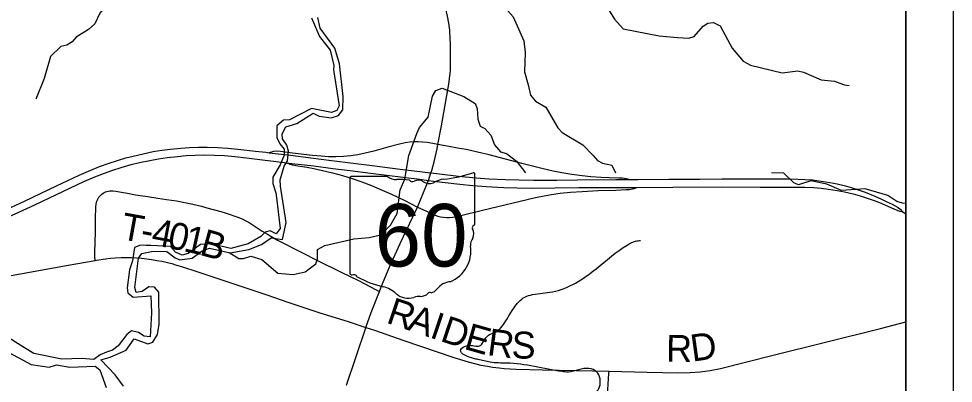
# Model space of a CAD drawing. Extents: x 0 to 34, y 0 to 22.
# Drawn here: x 28.944 to 30.917, y 17.017 to 17.785 of the extents above; entities that cross this region are included whole.
import ezdxf

# ---------------------------------------------------------------- set-up
doc = ezdxf.new("R2010")
doc.units = 0
for name, color, linetype in [('GM_X_Adjacent_County', 7, 'Continuous'), ('GM_X_County', 7, 'Continuous'), ('GM_X_County_Road', 7, 'Continuous'), ('GM_X_County_Road_Text', 7, 'Continuous'), ('GM_X_Interchange_Ramps', 7, 'Continuous'), ('GM_X_Minor_River', 7, 'Continuous'), ('GM_X_State_Location', 7, 'Continuous'), ('GM_X_State_Route', 7, 'Continuous'), ('GM_X_State_Shield', 7, 'Continuous'), ('GM_X_Township', 7, 'Continuous'), ('GM_X_Township_Road', 7, 'Continuous'), ('GM_X_Township_Road_Text', 7, 'Continuous'), ('SH_Data', 7, 'Continuous')]:
    doc.layers.add(name, color=color, linetype=linetype)

msp = doc.modelspace()

# ---------------------------------------------------------------- linework, layer by layer
at = {"layer": 'GM_X_Adjacent_County'}
msp.add_lwpolyline([(24.0167, 18.0693), (24.0167, 14.1), (30.8167, 14.1), (30.8167, 17.8174)], dxfattribs=at)
at = {"layer": 'GM_X_County'}
msp.add_lwpolyline([(24.0167, 18.0693), (24.0167, 14.1), (30.8167, 14.1), (30.8167, 17.8174)], dxfattribs=at)
at = {"layer": 'GM_X_County_Road'}
for points in [[(29.1052, 17.2759), (29.1086, 17.2765), (29.1274, 17.2793), (29.1381, 17.2807), (29.1477, 17.2813), (29.1602, 17.2819), (29.1819, 17.2817), (29.2036, 17.2803), (29.2146, 17.2791), (29.2247, 17.2777), (29.2359, 17.2758), (29.2464, 17.274), (29.2676, 17.269), (29.2773, 17.266), (29.2881, 17.2628), (29.3224, 17.2516), (29.468, 17.203), (29.5121, 17.188), (29.58, 17.1655), (29.6393, 17.147), (29.6771, 17.1346)], [(28.37, 17.1425), (28.4294, 17.1534), (28.6221, 17.1878), (28.7381, 17.2094), (28.8329, 17.2261), (28.8849, 17.2357), (28.9245, 17.2432), (28.9826, 17.2537), (29.0529, 17.2667), (29.1052, 17.2759)], [(30.19, 17.0422), (30.2702, 17.0401), (30.3355, 17.0389), (30.3604, 17.0392), (30.3821, 17.0409), (30.4037, 17.0438), (30.4251, 17.0481), (30.5337, 17.075), (30.7627, 17.1323), (30.8167, 17.1459)], [(29.6771, 17.1346), (29.6954, 17.1286), (29.7568, 17.1069), (29.8628, 17.0711), (29.8926, 17.0621), (29.9197, 17.0552), (29.9338, 17.0525), (29.9443, 17.051), (29.9582, 17.0493), (29.969, 17.0481), (29.9939, 17.0464), (30.0498, 17.0452), (30.1554, 17.0431), (30.19, 17.0422)], [(30.1819, 16.9257), (30.1821, 16.9277), (30.1846, 16.9586), (30.1896, 17.0372), (30.19, 17.0422)]]:
    msp.add_lwpolyline(points, dxfattribs=at)
at = {"layer": 'GM_X_Interchange_Ramps'}
for points in [[(29.829, 17.5202), (29.8182, 17.5221), (29.806, 17.5242), (29.7967, 17.5253), (29.7874, 17.5259), (29.7781, 17.5257), (29.7689, 17.5248), (29.7597, 17.5233), (29.7475, 17.5207), (29.7235, 17.5142), (29.6935, 17.5059), (29.6754, 17.5016), (29.6602, 17.4985), (29.6448, 17.4961), (29.6294, 17.4947), (29.6138, 17.4941), (29.5983, 17.4944), (29.5828, 17.4953), (29.5642, 17.497), (29.5223, 17.5019), (29.4965, 17.5052), (29.4879, 17.5058), (29.4816, 17.505), (29.473, 17.5027)], [(30.2324, 17.4461), (30.227, 17.448), (30.2186, 17.4491), (30.2107, 17.4493), (30.19, 17.4497), (30.1732, 17.4504), (30.1516, 17.4521), (30.1331, 17.4541), (30.1116, 17.457), (30.0902, 17.4605), (30.0719, 17.464), (30.0508, 17.4689), (30.0058, 17.4804), (29.9368, 17.4985), (29.9127, 17.5042), (29.8884, 17.5093), (29.8701, 17.5126), (29.8487, 17.5163), (29.829, 17.5202)], [(29.5101, 17.4817), (29.5163, 17.4785), (29.5214, 17.4773), (29.5332, 17.4749), (29.5521, 17.4724), (29.5672, 17.4696), (29.5853, 17.4656), (29.6063, 17.4604), (29.6272, 17.4546), (29.6478, 17.4482), (29.6683, 17.4411), (29.6885, 17.4335), (29.7114, 17.4241), (29.7311, 17.4153), (29.759, 17.402), (29.7856, 17.3883)], [(29.7856, 17.3883), (29.7973, 17.3828), (29.817, 17.3736), (29.8228, 17.3712), (29.8287, 17.3692), (29.8347, 17.3677), (29.8408, 17.3668), (29.847, 17.3663), (29.8532, 17.3664), (29.8594, 17.367), (29.8655, 17.3679), (29.8776, 17.3705), (29.923, 17.3814), (30.0347, 17.4082), (30.053, 17.412), (30.0683, 17.4147), (30.0867, 17.4172), (30.1084, 17.4194), (30.1332, 17.4212), (30.1673, 17.423), (30.2046, 17.4241), (30.2261, 17.425), (30.2325, 17.4254), (30.2395, 17.4265), (30.2428, 17.4273), (30.2489, 17.4294)]]:
    msp.add_lwpolyline(points, dxfattribs=at)
at = {"layer": 'GM_X_Minor_River'}
for points in [[(29.2198, 17.8553), (29.1892, 17.8486), (29.1658, 17.8394), (29.1394, 17.8173), (29.1258, 17.8101), (29.1156, 17.7968), (29.1047, 17.7747), (29.0915, 17.7625), (29.0655, 17.7461), (29.0568, 17.7362), (29.0459, 17.7297), (29.0334, 17.727), (29.0111, 17.7053), (28.9981, 17.659), (28.9801, 17.6157)], [(29.9472, 17.8355), (29.9875, 17.7892), (30.0104, 17.7388), (30.0131, 17.7138), (30.0118, 17.6732), (30.0191, 17.6459), (30.0245, 17.6239), (30.0348, 17.6118), (30.0564, 17.5986), (30.082, 17.5554), (30.0915, 17.5452), (30.1347, 17.5196), (30.1564, 17.4972), (30.1659, 17.4867), (30.1762, 17.4806), (30.1963, 17.4765), (30.2039, 17.4602)], [(30.1743, 17.8295), (30.2014, 17.7846), (30.22, 17.7642), (30.2962, 17.7489), (30.3344, 17.7456), (30.3586, 17.7441), (30.3696, 17.748), (30.3884, 17.7693), (30.3986, 17.7758), (30.4104, 17.7773), (30.4248, 17.7702), (30.45, 17.7232), (30.4735, 17.696), (30.4884, 17.6873), (30.5554, 17.6712), (30.5883, 17.6751), (30.6005, 17.6729), (30.6376, 17.6563), (30.6657, 17.6538), (30.677, 17.6492), (30.6869, 17.6462), (30.6967, 17.6444)], [(29.1652, 17.0105), (29.1477, 17.0347), (29.1172, 17.0661), (29.1373, 17.0715), (29.1713, 17.0868), (29.1882, 17.1104), (29.2167, 17.1002), (29.2272, 17.1037), (29.2374, 17.1193), (29.2403, 17.1413), (29.2397, 17.2088), (29.2305, 17.2194), (29.2188, 17.2197), (29.2044, 17.2102), (29.192, 17.2083), (29.1893, 17.2189), (29.1973, 17.2807), (29.2037, 17.2903), (29.2279, 17.2953), (29.2567, 17.2946), (29.2742, 17.2814), (29.284, 17.2769), (29.3101, 17.2808), (29.3316, 17.296), (29.3468, 17.3014), (29.3907, 17.292), (29.4297, 17.2986), (29.4565, 17.3093), (29.4773, 17.3234), (29.5008, 17.3201), (29.5086, 17.3554), (29.4969, 17.432), (29.4961, 17.4453), (29.5046, 17.4741), (29.5118, 17.4856), (29.5136, 17.506), (29.5101, 17.5185), (29.5006, 17.5322), (29.5002, 17.5428), (29.5081, 17.5572), (29.5315, 17.5641), (29.5659, 17.5859), (29.578, 17.5799), (29.6038, 17.5762), (29.6193, 17.5811), (29.6283, 17.5929), (29.6289, 17.6214), (29.6211, 17.69), (29.6111, 17.723), (29.5806, 17.7654), (29.5756, 17.7881)], [(29.5623, 17.7873), (29.5788, 17.7479), (29.6013, 17.7192), (29.609, 17.6869), (29.6082, 17.6775), (29.6203, 17.6016), (29.6158, 17.5921), (29.6041, 17.5879), (29.562, 17.5961), (29.5156, 17.5724), (29.5031, 17.5713), (29.4888, 17.5598), (29.4892, 17.5348), (29.495, 17.5212), (29.5041, 17.5106), (29.5042, 17.4977), (29.4959, 17.4771), (29.4805, 17.4509), (29.4806, 17.4376), (29.4871, 17.4179), (29.4883, 17.4077), (29.4957, 17.3432), (29.4878, 17.3318), (29.4746, 17.3379), (29.464, 17.3355), (29.4549, 17.326), (29.4281, 17.3104), (29.3918, 17.3008), (29.3498, 17.3109), (29.3278, 17.3096), (29.3021, 17.2906), (29.2893, 17.2871), (29.2753, 17.2932)], [(29.3887, 17.2925), (29.4089, 17.28), (29.4188, 17.2796), (29.4339, 17.2846), (29.457, 17.2779), (29.4908, 17.2491), (29.5234, 17.2462), (29.5487, 17.252), (29.5714, 17.2688), (29.5751, 17.2794), (29.575, 17.2984), (29.5902, 17.3075), (29.6514, 17.321), (29.6836, 17.3238), (29.7085, 17.3296), (29.7183, 17.3394), (29.7289, 17.3497), (29.7432, 17.3744), (29.7494, 17.4242), (29.7588, 17.4473), (29.7673, 17.4967), (29.7841, 17.5434), (29.7901, 17.5559), (29.8082, 17.578), (29.8174, 17.622), (29.8242, 17.6338), (29.8382, 17.6388), (29.8833, 17.6215), (29.9072, 17.6064), (29.9118, 17.5962), (29.9134, 17.5738), (29.9184, 17.559), (29.9279, 17.5537), (29.9405, 17.5401), (29.9481, 17.5197), (29.9607, 17.5045), (29.9739, 17.5008), (29.9948, 17.4849), (30.0139, 17.4607)], [(30.8167, 17.3957), (30.8095, 17.3963), (30.7974, 17.4), (30.7787, 17.4129), (30.7306, 17.4264), (30.681, 17.4228), (30.6499, 17.4363), (30.6162, 17.4434), (30.5898, 17.435), (30.5799, 17.4391), (30.559, 17.4595), (30.5332, 17.4602)], [(29.2753, 17.2932), (29.2642, 17.3049), (29.2233, 17.307), (29.2135, 17.307), (29.2014, 17.3081), (29.1889, 17.3027), (29.1845, 17.275), (29.1781, 17.256), (29.173, 17.2177), (29.1746, 17.2075), (29.186, 17.198), (29.2227, 17.2011), (29.2246, 17.1653), (29.2215, 17.1147), (29.209, 17.1161), (29.1969, 17.1241), (29.1825, 17.1271), (29.1723, 17.1198), (29.1542, 17.0958), (29.1418, 17.0867), (29.1297, 17.0821), (29.1161, 17.0767), (29.1029, 17.0665), (29.0771, 17.069), (29.0351, 17.0677), (28.976, 17.0793), (28.9566, 17.0914), (28.8834, 17.137)], [(28.9234, 17.0818), (28.9708, 17.0561), (29.0083, 17.051), (29.0242, 17.0559), (29.0522, 17.0507), (29.1052, 17.0528), (29.1154, 17.0449), (29.1285, 17.0077)]]:
    msp.add_lwpolyline(points, dxfattribs=at)
msp.add_spline([(29.8147, 15.9312), (29.8117, 15.9558), (29.7953, 15.9967), (29.7918, 16.0206), (29.7756, 16.0805), (29.7599, 16.1172), (29.7507, 16.154), (29.7354, 16.1926), (29.7112, 16.1945), (29.6991, 16.1906), (29.6835, 16.1917), (29.6733, 16.1981), (29.6402, 16.2337), (29.6394, 16.2473), (29.6397, 16.2621), (29.6471, 16.2929), (29.6459, 16.3122), (29.6536, 16.3688), (29.6717, 16.3988), (29.7128, 16.432), (29.7245, 16.4426), (29.7448, 16.467), (29.7462, 16.492), (29.8196, 16.5139), (29.8122, 16.5556), (29.8085, 16.6246), (29.8106, 16.7498), (29.8172, 16.7988), (29.8262, 16.8208), (29.8348, 16.8338), (29.8458, 16.8433), (29.864, 16.8433), (29.8745, 16.8479), (29.8847, 16.8719), (29.8979, 16.8746), (29.9233, 16.8728), (29.9258, 16.8872), (29.933, 16.8993), (29.9633, 16.8991), (30.0196, 16.9087), (30.034, 16.9084), (30.062, 16.9199), (30.0963, 16.9428), (30.1243, 16.9645), (30.148, 16.9968), (30.162, 16.9984), (30.1699, 17.009), (30.1637, 17.0409), (30.1477, 17.048), (30.1042, 17.0403), (30.091, 17.0414), (29.9739, 17.0592), (29.9391, 17.061), (29.9137, 17.067), (29.9042, 17.0688), (29.8769, 17.0866), (29.892, 17.0965), (29.917, 17.0954), (29.9355, 17.1179), (29.9506, 17.1244), (29.9611, 17.1331), (29.989, 17.1753), (30.0127, 17.1986), (30.0286, 17.2036), (30.0706, 17.2094), (30.1631, 17.2583), (30.2284, 17.3082), (30.2462, 17.3162), (30.2567, 17.3178)], degree=3, dxfattribs=at)
at = {"layer": 'GM_X_State_Route'}
for points in [[(29.8553, 17.68), (29.8557, 17.6886), (29.8556, 17.7322), (29.8551, 17.7432), (29.8541, 17.7609), (29.8523, 17.7756), (29.8494, 17.791), (29.8453, 17.806), (29.84, 17.8207), (29.8296, 17.8449)], [(29.829, 17.5202), (29.8363, 17.5596), (29.8526, 17.6514), (29.8536, 17.6591), (29.8543, 17.6649), (29.8548, 17.6701), (29.8552, 17.6771), (29.8553, 17.68)], [(29.8055, 17.436), (29.8088, 17.4444), (29.8142, 17.4604), (29.8158, 17.4654), (29.8209, 17.4834), (29.8272, 17.5107), (29.829, 17.5202)], [(28.9103, 17.362), (28.9444, 17.3771), (28.9781, 17.3928), (29.0537, 17.4291), (29.0819, 17.4421), (29.1048, 17.4519), (29.125, 17.4599), (29.1426, 17.4662), (29.1604, 17.4718), (29.1813, 17.4777), (29.1994, 17.4822), (29.2207, 17.4867), (29.2391, 17.4899), (29.2576, 17.4926), (29.2792, 17.4951), (29.2978, 17.4966), (29.3164, 17.4976), (29.3351, 17.498), (29.3568, 17.4977), (29.3786, 17.4966), (29.4002, 17.4949), (29.425, 17.4923), (29.5101, 17.4817), (29.5205, 17.4804), (29.5667, 17.4748), (29.6068, 17.4698), (29.6438, 17.465), (29.6869, 17.4594), (29.7899, 17.4467)], [(28.92, 17.3839), (28.9566, 17.4009), (29.0238, 17.4331), (29.0716, 17.4556), (29.0914, 17.4642), (29.1145, 17.4734), (29.1349, 17.4808), (29.1526, 17.4866), (29.1704, 17.4918), (29.1854, 17.4957), (29.2066, 17.5006), (29.2278, 17.505), (29.2462, 17.508), (29.2646, 17.5104), (29.2862, 17.5126), (29.3048, 17.5139), (29.3234, 17.5145), (29.342, 17.5146), (29.3637, 17.514), (29.3853, 17.5127), (29.4069, 17.5106), (29.4439, 17.5062), (29.4655, 17.5036), (29.473, 17.5027), (29.5179, 17.4974), (29.561, 17.4917), (29.6041, 17.4864), (29.6504, 17.4806), (29.6904, 17.4756), (29.749, 17.4684), (29.8142, 17.4604), (29.8322, 17.4582), (29.8724, 17.4535), (29.9095, 17.45), (29.9374, 17.4479), (29.9715, 17.4462), (29.9995, 17.4453), (30.0305, 17.445), (30.0802, 17.4451), (30.1237, 17.4454), (30.2045, 17.446), (30.2324, 17.4461), (30.251, 17.4462), (30.3162, 17.4467), (30.3815, 17.4472), (30.4281, 17.4475), (30.5514, 17.4476), (30.5669, 17.4476), (30.5885, 17.4473), (30.604, 17.4465), (30.6194, 17.4453), (30.6378, 17.4431), (30.6562, 17.4402), (30.6714, 17.4371), (30.6864, 17.4335), (30.7013, 17.4293), (30.7161, 17.4247), (30.7306, 17.4194), (30.7507, 17.4113), (30.7649, 17.405), (30.7751, 17.4), (30.7876, 17.394), (30.8002, 17.387), (30.8043, 17.3838), (30.809, 17.3791)], [(29.7899, 17.4467), (29.8088, 17.4444), (29.8194, 17.4431), (29.8749, 17.4365), (29.9027, 17.4337), (29.9306, 17.4316), (29.9677, 17.4295), (29.9957, 17.4286), (30.0267, 17.4282), (30.0764, 17.4285), (30.1261, 17.4292), (30.2379, 17.4294), (30.2489, 17.4294), (30.3248, 17.4299), (30.4304, 17.4306), (30.5089, 17.4304)], [(29.6771, 17.1346), (29.6877, 17.1656), (29.7053, 17.2105), (29.7081, 17.2176), (29.7275, 17.2634), (29.749, 17.3116), (29.7758, 17.3676), (29.7856, 17.3883), (29.7878, 17.393), (29.7988, 17.4187), (29.8055, 17.436)], [(30.5089, 17.4304), (30.5409, 17.4303), (30.5815, 17.4305), (30.6034, 17.4301), (30.6221, 17.4292), (30.6376, 17.4279), (30.6531, 17.4261), (30.6717, 17.4232), (30.687, 17.4203), (30.7053, 17.4161), (30.7203, 17.412), (30.7352, 17.4073), (30.7499, 17.4021), (30.7608, 17.3978), (30.7912, 17.3844), (30.7998, 17.381), (30.8034, 17.3798), (30.809, 17.3791)], [(30.809, 17.3791), (30.8167, 17.3741)], [(29.6362, 17.0125), (29.6766, 17.1333), (29.6771, 17.1346)]]:
    msp.add_lwpolyline(points, dxfattribs=at)
at = {"layer": 'GM_X_State_Shield'}
for p, q in [((29.9067, 17.3526), (29.9067, 17.4573)), ((29.643, 17.4489), (29.643, 17.2488)), ((29.7229, 17.4523), (29.6456, 17.4523)), ((29.9067, 17.3526), (29.9067, 17.3526))]:
    msp.add_line(p, q, dxfattribs=at)
for centre, radius, start, end in [((29.8128, 17.7252), 0.2796, 275.8445, 288.9065), ((29.9038, 17.4577), 0.00294, 351.8621, 97.738), ((29.6461, 17.4493), 0.00305, 98.1301, 188.1301), ((29.7412, 17.4756), 0.0296, 231.6195, 271.1119), ((29.7511, 17.34), 0.1064, 80.4867, 94.9883), ((29.7752, 17.4504), 0.00855, 219.7921, 297.1024), ((29.7878, 17.4272), 0.0178, 54.4667, 119.1411), ((29.8107, 17.459), 0.0214, 233.8562, 294.8282), ((29.8485, 17.3912), 0.0563, 97.3462, 120.7689), ((29.906, 17.3449), 0.00454, 107.944, 210.337), ((29.8771, 17.3317), 0.0273, 340.033, 23.6496), ((29.9036, 17.3522), 0.00314, 289.6038, 7.7341), ((29.9172, 17.3088), 0.0198, 136.8065, 186.9296), ((29.8285, 17.2955), 0.0699, 292.3089, 8.9858), ((29.6461, 17.2483), 0.00308, 171.9584, 258.3066), ((29.6466, 17.2688), 0.0235, 267.339, 280.6039), ((29.6514, 17.2372), 0.00848, 29.7484, 93.2717), ((29.7584, 17.417), 0.2019, 240.4129, 257.1985), ((29.8579, 17.1926), 0.0383, 94.4031, 142.5768), ((29.6982, 17.1589), 0.0632, 47.1842, 75.836), ((29.7666, 17.2362), 0.0401, 230.7004, 286.2918), ((29.7927, 17.2213), 0.0214, 268.777, 315.5493), ((29.812, 17.2019), 0.00601, 65.7517, 132.6484), ((29.8094, 17.2294), 0.0226, 282.8732, 323.2771), ((29.7897, 17.1671), 0.0329, 85.6951, 111.2099)]:
    msp.add_arc(centre, radius, start, end, dxfattribs=at)
at = {"layer": 'GM_X_Township'}
msp.add_line((30.8167, 15.629), (30.8167, 17.8174), dxfattribs=at)
at = {"layer": 'GM_X_Township_Road'}
msp.add_lwpolyline([(29.1052, 17.2759), (29.1051, 17.283), (29.1051, 17.2923), (29.1055, 17.3141), (29.1059, 17.3358), (29.1061, 17.3544), (29.1064, 17.3699), (29.1066, 17.3823), (29.107, 17.3885), (29.1079, 17.3945), (29.1091, 17.4005), (29.1102, 17.4034), (29.1116, 17.4062), (29.1132, 17.4088), (29.1152, 17.4112), (29.1173, 17.4135), (29.1196, 17.4156), (29.1221, 17.4174), (29.1248, 17.419), (29.1276, 17.4203), (29.1305, 17.4213), (29.1335, 17.422), (29.1366, 17.4224), (29.1397, 17.4225), (29.1428, 17.4224), (29.149, 17.4218), (29.1613, 17.4199), (29.1735, 17.4176), (29.1907, 17.4141), (29.2162, 17.4107), (29.2376, 17.4073), (29.256, 17.4042), (29.2775, 17.4011), (29.3114, 17.3946), (29.3299, 17.3898), (29.3412, 17.3866), (29.3708, 17.3786), (29.3797, 17.3758), (29.3885, 17.3729), (29.4003, 17.369), (29.4091, 17.3659), (29.4171, 17.363), (29.4235, 17.3594), (29.4304, 17.3555), (29.4411, 17.3489), (29.4582, 17.3374), (29.469, 17.3311), (29.4795, 17.3245), (29.4903, 17.3184), (29.5041, 17.3112), (29.5318, 17.2974), (29.543, 17.2919), (29.5734, 17.2764), (29.6262, 17.2502), (29.6598, 17.234), (29.6764, 17.2254), (29.6957, 17.2154), (29.7053, 17.2105)], dxfattribs=at)
at = {"layer": 'SH_Data'}
for points in [[(23.9167, 21), (30.9167, 21), (30.9167, 14), (23.9167, 14)], [(24.0167, 20.9), (30.8167, 20.9), (30.8167, 14.1), (24.0167, 14.1)]]:
    msp.add_lwpolyline(points, close=True, dxfattribs=at)

# ---------------------------------------------------------------- texts
at = {"layer": 'GM_X_County_Road_Text'}
for s, rotation, p in [('R', 341.3194, (29.7178, 17.1449)), ('A', 341.3185, (29.762, 17.13)), ('I', 341.3182, (29.8094, 17.114)), ('D', 341.4596, (29.8316, 17.1065)), ('E', 344.1267, (29.8818, 17.0897)), ('R', 352.3702, (29.9314, 17.0763)), ('S', 358.0633, (29.9838, 17.0696)), ('D', 7.9683, (30.366, 17.0622)), ('R', 359.317, (30.3102, 17.0621))]:
    msp.add_text(s, height=0.0568, rotation=rotation, dxfattribs=at).set_placement(p)
at = {"layer": 'GM_X_State_Location'}
msp.add_text('60', height=0.000189, rotation=0, dxfattribs=at).set_placement((29.7242, 17.3218))
for s in ['s', 'r']:
    msp.add_text(s, height=0.000189, dxfattribs=at).set_placement((29.7719, 17.3355))
at = {"layer": 'GM_X_State_Shield'}
msp.add_text('60', height=0.13184, dxfattribs=at).set_placement((29.6954, 17.2629))
at = {"layer": 'GM_X_Township_Road_Text'}
for s, rotation, p in [('T', 349.6978, (29.1572, 17.321)), ('4', 349.3014, (29.2219, 17.3092)), ('0', 348.3359, (29.2561, 17.3028)), ('1', 347.303, (29.2901, 17.2957)), ('B', 344.4519, (29.3235, 17.2882)), ('-', 349.6163, (29.199, 17.3134))]:
    msp.add_text(s, height=0.0568, rotation=rotation, dxfattribs=at).set_placement(p)

doc.saveas('drawing.dxf')
